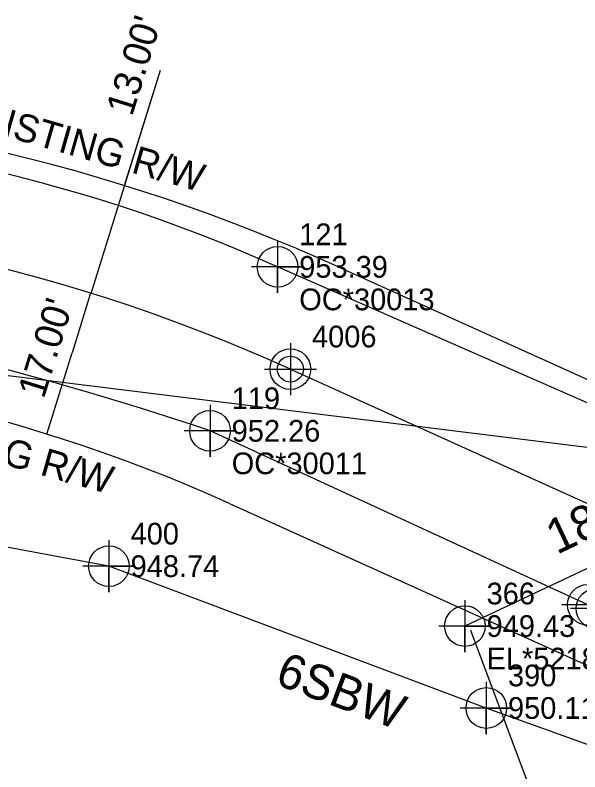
# Model space of a CAD drawing. Extents: x 1150279 to 1151282, y 654632 to 657999.
# Drawn here: x 1150844 to 1150909.2, y 657071.3 to 657158.5 of the extents above; entities that cross this region are included whole.
import ezdxf

# ---------------------------------------------------------------- set-up
doc = ezdxf.new("R2010")
doc.units = 0
for name, color, linetype in [('COGO Default Chain', 7, 'Continuous'), ('COGO Default Curve', 7, 'Continuous'), ('Cogo Default Point CELL', 7, 'Continuous'), ('COGO Default Point Number', 7, 'Continuous'), ('Exist Horizontal Alignment', 7, 'Continuous'), ('Exist Horizontal Alignment Station Label', 7, 'Continuous'), ('Exist Other Culture Fence Line', 7, 'Continuous'), ('Exist Other Culture Fence Line Cogo Elevation', 7, 'Continuous'), ('Exist Other Culture Fence Line Cogo Number', 7, 'Continuous'), ('Exist Other Culture Fence Line Cogo Point CELL', 7, 'Continuous'), ('Exist Other Culture Fence Line Text', 7, 'Continuous'), ('Exist Right of Way Line', 7, 'Continuous'), ('Exist Right of Way Line Text', 7, 'Continuous'), ('Exist Right of Way Width CELL', 7, 'Continuous'), ('Exist Roads EOP', 7, 'Continuous'), ('Exist Roads EOP Cogo Comment', 7, 'Continuous'), ('Exist Roads EOP Cogo Elevation', 7, 'Continuous'), ('Exist Roads EOP Cogo Number', 7, 'Continuous'), ('Exist Roads EOP Cogo Point CELL', 7, 'Continuous'), ('Exist Structure Minor Pipes CMP 15 Inch Leader', 7, 'Continuous'), ('Exist Structure Minor Pipes CMP 18 Inch', 7, 'Continuous'), ('Exist Structure Minor Pipes CMP 18 Inch Cogo Comment', 7, 'Continuous'), ('Exist Structure Minor Pipes CMP 18 Inch Cogo Elevation', 7, 'Continuous'), ('Exist Structure Minor Pipes CMP 18 Inch Cogo Number', 7, 'Continuous'), ('Exist Structure Minor Pipes CMP 18 Inch Cogo Point CELL', 7, 'Continuous'), ('Exist Structure Minor Pipes CMP 18 Inch Text', 7, 'Continuous')]:
    doc.layers.add(name, color=color, linetype=linetype)

msp = doc.modelspace()

# ---------------------------------------------------------------- linework, layer by layer
at = {"layer": 'COGO Default Chain'}
for p, q in [((1150614.756, 657145.261), (1150931.292, 657106.062)), ((1150875.785, 657117.706), (1150962.476, 657078.528))]:
    msp.add_line(p, q, dxfattribs=at)
msp.add_arc((1150793.42, 656935.454), 200, 65.68044, 91.66254, dxfattribs=at)
at = {"layer": 'COGO Default Curve'}
msp.add_arc((1150793.42, 656935.454), 200, 65.68044, 91.66254, dxfattribs=at)
at = {"layer": 'Cogo Default Point CELL'}
for points in [[(1150875.785, 657120.706), (1150875.785, 657117.706)], [(1150875.785, 657120.706), (1150875.785, 657117.706)], [(1150872.785, 657117.706), (1150875.785, 657117.706)], [(1150872.785, 657117.706), (1150875.785, 657117.706)], [(1150875.785, 657117.706), (1150878.785, 657117.706)], [(1150875.785, 657117.706), (1150875.785, 657114.706)], [(1150875.785, 657117.706), (1150878.785, 657117.706)], [(1150875.785, 657117.706), (1150875.785, 657114.706)]]:
    msp.add_lwpolyline(points, dxfattribs=at)
msp.add_circle((1150875.785, 657117.706), 2.344, dxfattribs=at)
msp.add_circle((1150875.785, 657117.706), 2.344, dxfattribs=at)
at = {"layer": 'Exist Horizontal Alignment'}
msp.add_line((1150875.785, 657117.706), (1150962.476, 657078.528), dxfattribs=at)
msp.add_arc((1150793.42, 656935.454), 200, 65.68044, 91.66254, dxfattribs=at)
at = {"layer": 'Exist Horizontal Alignment Station Label'}
msp.add_circle((1150875.785, 657117.706), 1.5, dxfattribs=at)
at = {"layer": 'Exist Other Culture Fence Line'}
msp.add_lwpolyline([(1151064.379, 657042.204), (1151035.792, 657039.664), (1150986.531, 657050.151), (1150941.416, 657063.204), (1150898.391, 657078.653), (1150854.858, 657094.994), (1150825.025, 657100.534), (1150812.457, 657091.594), (1150835.172, 657043.741), (1150852.719, 657007.431)], dxfattribs=at)
at = {"layer": 'Exist Other Culture Fence Line Cogo Point CELL'}
for points in [[(1150854.858, 657097.994), (1150854.858, 657091.994), (1150854.858, 657094.994), (1150857.858, 657094.994), (1150851.858, 657094.994)], [(1150898.391, 657081.653), (1150898.391, 657075.653), (1150898.391, 657078.653), (1150901.391, 657078.653), (1150895.391, 657078.653)]]:
    msp.add_lwpolyline(points, dxfattribs=at)
for centre in [(1150854.858, 657094.994), (1150898.391, 657078.653)]:
    msp.add_circle(centre, 2.344, dxfattribs=at)
at = {"layer": 'Exist Right of Way Line'}
for p, q in [((1150881.139, 657129.553), (1150942.356, 657101.887)), ((1150868.784, 657102.215), (1150930.001, 657074.549))]:
    msp.add_line(p, q, dxfattribs=at)
for radius, end in [(213, 88.72471), (183, 91.66254)]:
    msp.add_arc((1150793.42, 656935.454), radius, 65.68044, end, dxfattribs=at)
at = {"layer": 'Exist Right of Way Width CELL'}
for p, q in [((1150852.804, 657126.434), (1150860.796, 657152.137)), ((1150856.664, 657138.848), (1150860.796, 657152.137)), ((1150852.745, 657126.453), (1150850.613, 657119.59)), ((1150847.702, 657110.218), (1150850.613, 657119.59))]:
    msp.add_line(p, q, dxfattribs=at)
at = {"layer": 'Exist Roads EOP'}
for p, q in [((1150919.164, 657109.821), (1150874.311, 657129.486)), ((1150910.091, 657090.545), (1150866.518, 657110.593))]:
    msp.add_line(p, q, dxfattribs=at)
for centre, major_axis, ratio, start_param, end_param in [((1150800.442, 656964.8), (-177.198, 34.758), 0.999524, 4.48455, 4.91412), ((1150752.571, 656773.823), (-278.809, 220.877), 0.99945, 5.05593, 5.247845)]:
    msp.add_ellipse(centre, major_axis=major_axis, ratio=ratio, start_param=start_param, end_param=end_param, dxfattribs=at)
at = {"layer": 'Exist Roads EOP Cogo Point CELL'}
for points in [[(1150874.311, 657132.486), (1150874.311, 657126.486), (1150874.311, 657129.486), (1150877.311, 657129.486), (1150871.311, 657129.486)], [(1150866.518, 657113.593), (1150866.518, 657107.593), (1150866.518, 657110.593), (1150869.518, 657110.593), (1150863.518, 657110.593)], [(1150910.091, 657093.545), (1150910.091, 657087.545), (1150910.091, 657090.545), (1150913.091, 657090.545), (1150907.091, 657090.545)], [(1150911.093, 657093.114), (1150911.093, 657087.114), (1150911.093, 657090.114), (1150914.093, 657090.114), (1150908.093, 657090.114)]]:
    msp.add_lwpolyline(points, dxfattribs=at)
for centre in [(1150874.311, 657129.486), (1150866.518, 657110.593), (1150910.091, 657090.545), (1150911.093, 657090.114)]:
    msp.add_circle(centre, 2.344, dxfattribs=at)
at = {"layer": 'Exist Structure Minor Pipes CMP 15 Inch Leader'}
msp.add_lwpolyline([(1150896.558, 657087.609), (1150905.539, 657063.738), (1150898.675, 657064.498)], dxfattribs=at)
at = {"layer": 'Exist Structure Minor Pipes CMP 18 Inch'}
msp.add_line((1150936.288, 657107.106), (1150895.921, 657088.095), dxfattribs=at)
at = {"layer": 'Exist Structure Minor Pipes CMP 18 Inch Cogo Point CELL'}
msp.add_lwpolyline([(1150895.921, 657091.095), (1150895.921, 657085.095), (1150895.921, 657088.095), (1150898.921, 657088.095), (1150892.921, 657088.095)], dxfattribs=at)
msp.add_circle((1150895.921, 657088.095), 2.344, dxfattribs=at)

# ---------------------------------------------------------------- texts
at = {"layer": 'COGO Default Point Number'}
msp.add_text('4006', height=2.5, dxfattribs=at).set_placement((1150878.285, 657120.206))
at = {"layer": 'Exist Other Culture Fence Line Cogo Elevation'}
for s, p in [('948.74', (1150857.358, 657093.745)), ('950.11', (1150900.891, 657077.403))]:
    msp.add_text(s, height=2.5, dxfattribs=at).set_placement(p)
at = {"layer": 'Exist Other Culture Fence Line Cogo Number'}
for s, p in [('400', (1150857.358, 657097.495)), ('390', (1150900.891, 657081.153))]:
    msp.add_text(s, height=2.5, dxfattribs=at).set_placement(p)
at = {"layer": 'Exist Other Culture Fence Line Text'}
msp.add_text('6SBW', height=4, rotation=339.42472, dxfattribs=at).set_placement((1150873.881, 657081.445))
at = {"layer": 'Exist Right of Way Line Text'}
for rotation, p in [(344.0874, (1150836.967, 657146.19)), (344.27394, (1150826.415, 657111.293))]:
    msp.add_text('EXISTING R/W', height=3.2, rotation=rotation, dxfattribs=at).set_placement(p)
at = {"layer": 'Exist Right of Way Width CELL'}
for s, rotation, p in [("13.00'", 72.72724, (1150857.522, 657146.743)), ("17.00'", 72.7451, (1150847.341, 657114.195))]:
    msp.add_text(s, height=3.2, rotation=rotation, dxfattribs=at).set_placement(p)
at = {"layer": 'Exist Roads EOP Cogo Comment'}
for s, p in [('OC*30013', (1150876.811, 657124.486)), ('OC*30011', (1150869.018, 657105.593))]:
    msp.add_text(s, height=2.5, dxfattribs=at).set_placement(p)
at = {"layer": 'Exist Roads EOP Cogo Elevation'}
for s, p in [('953.39', (1150876.811, 657128.236)), ('952.26', (1150869.018, 657109.343))]:
    msp.add_text(s, height=2.5, dxfattribs=at).set_placement(p)
at = {"layer": 'Exist Roads EOP Cogo Number'}
for s, p in [('121', (1150876.811, 657131.986)), ('119', (1150869.018, 657113.093))]:
    msp.add_text(s, height=2.5, dxfattribs=at).set_placement(p)
at = {"layer": 'Exist Structure Minor Pipes CMP 18 Inch Cogo Comment'}
msp.add_text('EL*521827', height=2.5, dxfattribs=at).set_placement((1150898.421, 657083.095))
at = {"layer": 'Exist Structure Minor Pipes CMP 18 Inch Cogo Elevation'}
msp.add_text('949.43', height=2.5, dxfattribs=at).set_placement((1150898.421, 657086.845))
at = {"layer": 'Exist Structure Minor Pipes CMP 18 Inch Cogo Number'}
msp.add_text('366', height=2.5, dxfattribs=at).set_placement((1150898.421, 657090.595))
at = {"layer": 'Exist Structure Minor Pipes CMP 18 Inch Text'}
msp.add_text('18" CMP', height=4, rotation=25.21932, dxfattribs=at).set_placement((1150906.519, 657096.292))

doc.saveas('drawing.dxf')
